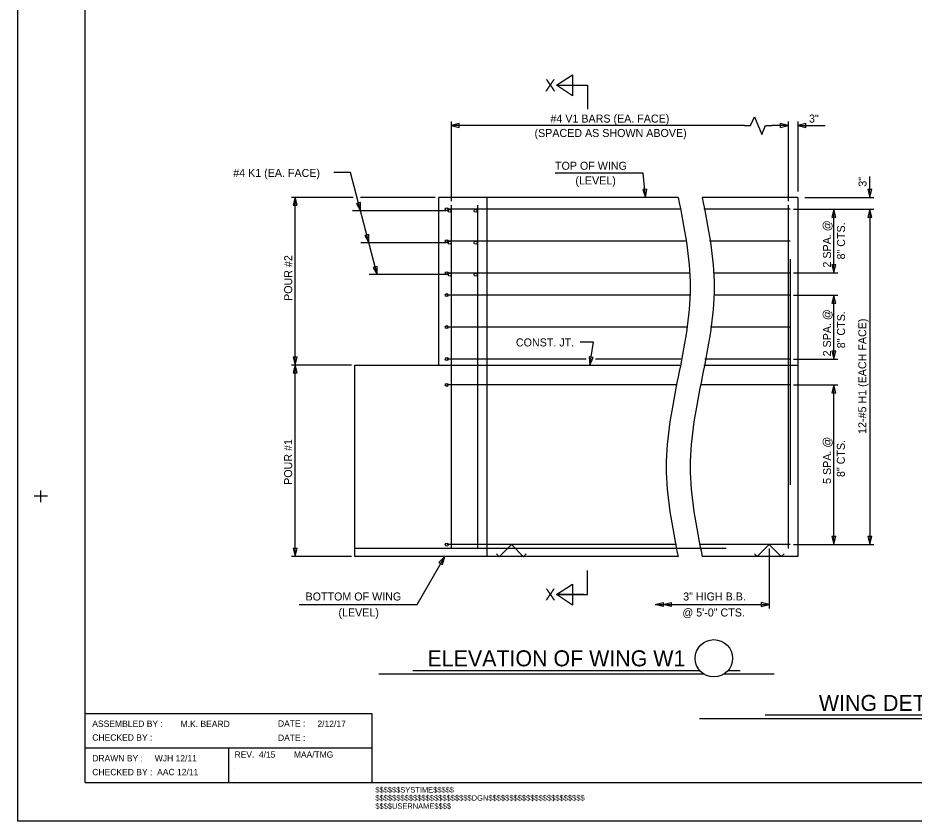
# Model space of a CAD drawing. Extents: x -41 to 251, y -169 to 237.
# Drawn here: x 0 to 18.71, y -98.91 to -82.14 of the extents above; entities that cross this region are included whole.
import ezdxf

# ---------------------------------------------------------------- set-up
doc = ezdxf.new("R2010")
doc.units = 0
for name, color, linetype in [('Arrowhead Terminators CELL', 7, 'Continuous'), ('Beam Bolsters CELL', 7, 'Continuous'), ('Default', 7, 'Continuous'), ('Dimension Lines', 7, 'Continuous'), ('Mis Object Lines', 7, 'Continuous'), ('Mis Object Lines Hidden', 7, 'Continuous'), ('Plan Sheet', 7, 'Continuous'), ('Plan Sheet CELL', 7, 'Continuous'), ('Plot Label CELL', 7, 'Continuous'), ('Plot Shape CELL', 7, 'Continuous'), ('Rebar K Bar Lines', 7, 'Continuous'), ('Rebar Lines', 7, 'Continuous'), ('Subtitle Text', 7, 'Continuous'), ('Text', 7, 'Continuous'), ('Title Text', 7, 'Continuous'), ('User Information Notes', 7, 'Continuous'), ('User Information Notes CELL', 7, 'Continuous')]:
    doc.layers.add(name, color=color, linetype=linetype)

# ---------------------------------------------------------------- blocks, each defined once
blk = doc.blocks.new('3 HIGH BEAM BOLSTER')
at = {"layer": 'Default'}
blk.add_lwpolyline([(-0.31, -0.192), (-0.251, -0.251), (0, 0), (0.251, -0.251), (0.31, -0.192)], dxfattribs=at)
blk = doc.blocks.new('SECSYM')
at = {"layer": 'Arrowhead Terminators CELL'}
blk.add_lwpolyline([(0, 0), (-2.48, 1.65), (-2.48, -1.65)], close=True, dxfattribs=at)

msp = doc.modelspace()

# ---------------------------------------------------------------- linework, layer by layer
at = {"layer": 'Arrowhead Terminators CELL'}
for points in [[(9.046, -84.389), (9.213, -84.43), (9.213, -84.347)], [(16.076, -84.389), (15.91, -84.347), (15.91, -84.43)], [(16.283, -84.389), (16.45, -84.43), (16.45, -84.347)], [(13.1, -85.889), (13.125, -85.719), (13.042, -85.727)], [(17.783, -85.889), (17.825, -85.722), (17.742, -85.722)], [(5.785, -85.889), (5.743, -86.055), (5.826, -86.055)], [(7.15, -86.17), (7.148, -85.998), (7.068, -86.02)], [(17.033, -86.139), (16.992, -86.305), (17.075, -86.305)], [(17.783, -86.139), (17.742, -86.305), (17.825, -86.305)], [(7.325, -86.836), (7.323, -86.665), (7.243, -86.686)], [(7.5, -87.503), (7.498, -87.332), (7.418, -87.353)], [(17.033, -87.466), (17.075, -87.299), (16.992, -87.299)], [(17.033, -87.93), (16.992, -88.096), (17.075, -88.096)], [(5.785, -89.389), (5.826, -89.222), (5.743, -89.222)], [(11.936, -89.389), (12.005, -89.232), (11.923, -89.218)], [(17.033, -89.264), (17.075, -89.097), (16.992, -89.097)], [(5.785, -89.389), (5.743, -89.555), (5.826, -89.555)], [(17.033, -89.805), (16.992, -89.971), (17.075, -89.971)], [(17.033, -93.139), (17.075, -92.972), (16.992, -92.972)], [(17.783, -93.139), (17.825, -92.972), (17.742, -92.972)], [(5.785, -93.389), (5.826, -93.222), (5.743, -93.222)], [(8.908, -93.389), (8.789, -93.512), (8.861, -93.553)], [(13.302, -94.389), (13.468, -94.347), (13.468, -94.43)], [(13.468, -94.389), (13.635, -94.347), (13.635, -94.43)], [(15.684, -94.389), (15.518, -94.347), (15.518, -94.43)]]:
    msp.add_lwpolyline(points, close=True, dxfattribs=at)
at = {"layer": 'Beam Bolsters CELL'}
msp.add_lwpolyline([(15.374, -93.33), (15.433, -93.389), (15.684, -93.139), (15.935, -93.389), (15.994, -93.33)], dxfattribs=at)
at = {"layer": 'Default'}
msp.add_lwpolyline([(15.167, -84.389), (15.295, -84.389), (15.377, -84.21), (15.531, -84.576), (15.608, -84.389), (15.739, -84.389)], dxfattribs=at)
at = {"layer": 'Dimension Lines'}
for p, q in [((11.245, -83.549), (11.888, -83.549)), ((11.888, -83.549), (11.888, -84.048)), ((9.046, -84.305), (9.046, -85.972)), ((16.076, -84.305), (16.076, -85.972)), ((16.283, -84.305), (16.283, -85.766)), ((15.167, -84.389), (9.046, -84.389)), ((16.076, -84.389), (15.739, -84.389)), ((16.283, -84.389), (16.848, -84.389)), ((6.941, -85.373), (6.596, -85.373)), ((7.5, -87.503), (6.941, -85.373)), ((13.05, -85.385), (11.217, -85.385)), ((13.1, -85.889), (13.05, -85.385)), ((17.783, -85.889), (17.783, -85.457)), ((7, -85.889), (5.713, -85.889)), ((5.785, -89.389), (5.785, -85.889)), ((8.713, -85.889), (7.15, -85.889)), ((16.423, -85.889), (17.867, -85.889)), ((8.931, -86.17), (6.984, -86.17)), ((16.189, -86.139), (17.867, -86.139)), ((17.033, -87.466), (17.033, -86.139)), ((17.783, -86.139), (17.783, -93.139)), ((8.931, -86.836), (7.159, -86.836)), ((8.931, -87.503), (7.334, -87.503)), ((16.189, -87.466), (17.117, -87.466)), ((16.189, -87.93), (17.117, -87.93)), ((17.033, -89.264), (17.033, -87.93)), ((12.017, -88.912), (11.736, -88.912)), ((11.936, -89.389), (12.017, -88.912)), ((6.963, -89.389), (5.713, -89.389)), ((5.785, -93.389), (5.785, -89.389)), ((16.189, -89.264), (17.117, -89.264)), ((16.189, -89.805), (17.117, -89.805)), ((17.033, -93.139), (17.033, -89.805)), ((16.189, -93.139), (17.867, -93.139)), ((15.684, -93.222), (15.684, -94.472)), ((6.963, -93.389), (5.712, -93.389)), ((11.888, -94.181), (11.888, -93.681)), ((11.81, -94.181), (11.245, -94.181)), ((11.245, -94.181), (11.888, -94.181)), ((13.302, -94.389), (15.684, -94.389))]:
    msp.add_line(p, q, dxfattribs=at)
msp.add_lwpolyline([(5.868, -94.389), (8.331, -94.389), (8.908, -93.389)], dxfattribs=at)
for points in [[(13.781, -85.889), (14.031, -87.764), (13.781, -89.639), (13.531, -91.514), (13.781, -93.389)], [(14.283, -85.889), (14.533, -87.764), (14.283, -89.639), (14.033, -91.514), (14.283, -93.389)]]:
    msp.add_spline(points, degree=3, dxfattribs=at)
at = {"layer": 'Mis Object Lines'}
for p, q in [((8.785, -89.389), (8.785, -85.889)), ((13.781, -85.889), (8.785, -85.889)), ((16.283, -85.889), (14.283, -85.889)), ((16.283, -85.889), (16.283, -93.389)), ((7.035, -93.389), (7.035, -89.389)), ((7.035, -89.389), (8.785, -89.389)), ((13.781, -93.389), (7.035, -93.389)), ((16.283, -93.389), (14.283, -93.389))]:
    msp.add_line(p, q, dxfattribs=at)
at = {"layer": 'Mis Object Lines Hidden'}
for p, q in [((9.785, -85.889), (9.785, -93.389)), ((8.785, -89.389), (13.819, -89.389)), ((14.321, -89.389), (16.283, -89.389))]:
    msp.add_line(p, q, dxfattribs=at)
at = {"layer": 'Plan Sheet CELL'}
for p, q in [((1.402, -98.104), (1.402, -70.174)), ((0.475, -92.25), (0.475, -92.009)), ((0.339, -92.119), (0.619, -92.119)), ((1.402, -96.661), (7.387, -96.661)), ((7.387, -96.661), (7.387, -97.382)), ((1.402, -97.382), (7.387, -97.382)), ((4.394, -97.382), (4.394, -98.104)), ((7.387, -97.382), (7.387, -98.104)), ((1.402, -98.104), (43.962, -98.104)), ((0, -98.91), (0, -98.91))]:
    msp.add_line(p, q, dxfattribs=at)
at = {"layer": 'Plot Shape CELL'}
msp.add_lwpolyline([(0, -69.65), (43.974, -69.65), (43.974, -98.91), (0, -98.91)], close=True, dxfattribs=at)
at = {"layer": 'Rebar K Bar Lines'}
for centre in [(9.014, -86.17), (9.556, -86.17), (9.014, -86.836), (9.556, -86.836), (9.014, -87.503), (9.556, -87.503)]:
    msp.add_circle(centre, 0.0312, dxfattribs=at)
at = {"layer": 'Rebar Lines'}
for p, q in [((13.819, -86.139), (8.952, -86.139)), ((9.046, -86.055), (9.046, -93.222)), ((9.59, -86.055), (9.59, -93.222)), ((16.117, -86.139), (14.321, -86.139)), ((16.076, -86.055), (16.076, -93.222)), ((13.934, -86.805), (8.952, -86.805)), ((16.117, -86.805), (14.436, -86.805)), ((14.02, -87.472), (8.952, -87.472)), ((16.117, -87.472), (14.522, -87.472)), ((14.028, -87.93), (8.952, -87.93)), ((16.117, -87.93), (14.53, -87.93)), ((13.955, -88.597), (8.952, -88.597)), ((16.117, -88.597), (14.457, -88.597)), ((11.865, -89.264), (8.952, -89.264)), ((13.839, -89.264), (12.053, -89.264)), ((16.117, -89.264), (14.341, -89.264)), ((13.757, -89.805), (8.952, -89.805)), ((16.117, -89.805), (14.259, -89.805)), ((13.744, -93.139), (8.952, -93.139)), ((16.117, -93.139), (14.246, -93.139))]:
    msp.add_line(p, q, dxfattribs=at)
for centre in [(8.952, -86.139), (8.952, -86.805), (8.952, -87.472), (8.952, -87.93), (8.952, -88.597), (8.952, -89.264), (8.952, -89.805), (8.952, -93.139)]:
    msp.add_circle(centre, 0.0312, dxfattribs=at)
at = {"layer": 'Title Text'}
for p, q in [((8.244, -95.763), (14.229, -95.763)), ((14.825, -95.763), (15.074, -95.763)), ((7.532, -95.837), (14.313, -95.837)), ((14.742, -95.837), (15.786, -95.837)), ((15.601, -96.694), (21.587, -96.694)), ((14.226, -96.768), (22.963, -96.768)), ((14.89, -96.768), (21.67, -96.768))]:
    msp.add_line(p, q, dxfattribs=at)
msp.add_circle((14.527, -95.512), 0.39, dxfattribs=at)
at = {"layer": 'User Information Notes'}
for p, q in [((4.524, -97.576), (4.524, -97.576)), ((4.524, -97.807), (4.524, -97.807)), ((4.524, -98.027), (4.524, -98.027))]:
    msp.add_line(p, q, dxfattribs=at)
at = {"layer": 'User Information Notes CELL'}
for p, q in [((16.117, -87.179), (16.117, -91.889)), ((14.785, -93.222), (7.035, -93.222))]:
    msp.add_line(p, q, dxfattribs=at)

# ---------------------------------------------------------------- block references
at = {"layer": 'Dimension Lines', "xscale": 0.1331292, "yscale": -0.133130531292, "rotation": 180}
for p in [(11.245, -83.549), (11.245, -94.181)]:
    msp.add_blockref('SECSYM', p, dxfattribs=at)
at = {"layer": 'Rebar Lines', "yscale": -1.00001, "rotation": 180}
msp.add_blockref('3 HIGH BEAM BOLSTER', (10.3, -93.139), dxfattribs=at)

# ---------------------------------------------------------------- texts
at = {"layer": 'Plan Sheet'}
msp.add_text('REV.  4/15        MAA/TMG', height=0.13124, dxfattribs=at).set_placement((4.524, -97.587))
at = {"layer": 'Plan Sheet CELL'}
for s, height, p in [('ASSEMBLED BY :', 0.13299, (1.552, -96.944)), ('DATE :', 0.133, (5.428, -96.94)), ('CHECKED BY :', 0.13299, (1.552, -97.232)), ('DATE :', 0.133, (5.428, -97.237)), ('DRAWN BY :     WJH 12/11', 0.13299, (1.552, -97.665)), ('CHECKED BY :  AAC 12/11', 0.13299, (1.552, -97.953))]:
    msp.add_text(s, height=height, dxfattribs=at).set_placement(p)
at = {"layer": 'Plot Label CELL'}
for s, height, p in [('$$$$$$SYSTIME$$$$$', 0.1131, (7.461, -98.314)), ('$$$$$$$$$$$$$$$$$$$$$$$DGN$$$$$$$$$$$$$$$$$$$$$$$', 0.11379, (7.461, -98.483)), ('$$$$USERNAME$$$$', 0.1131, (7.461, -98.653))]:
    msp.add_text(s, height=height, dxfattribs=at).set_placement(p)
at = {"layer": 'Subtitle Text'}
for p in [(11.001, -83.673), (11.001, -94.305)]:
    msp.add_text('X', height=0.25, dxfattribs=at).set_placement(p)
at = {"layer": 'Text'}
for s, rotation, p in [('#4 V1 BARS (EA. FACE)', 360, (11.116, -84.328)), ('3"', 360, (16.513, -84.327)), ('#4 K1 (EA. FACE)', 360, (4.494, -85.463)), ('TOP OF WING', 360, (11.211, -85.313)), ('(LEVEL)', 360, (11.637, -85.62)), ('3"', 90, (17.714, -85.667)), ('2 SPA. @', 90, (16.972, -87.354)), ('8" CTS.', 90, (17.265, -87.186)), ('POUR #2', 90, (5.725, -88.051)), ('2 SPA. @', 90, (16.972, -89.209)), ('8" CTS.', 90, (17.265, -89.04)), ('12-#5 H1 (EACH FACE)', 90, (17.709, -90.827)), ('CONST. JT.', 360, (10.395, -89.001)), ('5 SPA. @', 90, (16.973, -91.871)), ('POUR #1', 90, (5.724, -91.891)), ('8" CTS.', 90, (17.261, -91.728))]:
    msp.add_text(s, height=0.167, rotation=rotation, dxfattribs=at).set_placement(p)
for s, height, p in [(' (SPACED AS SHOWN ABOVE)', 0.167, (10.721, -84.629)), ('BOTTOM OF WING', 0.167, (6.004, -94.305)), ('3" HIGH B.B.', 0.167, (13.887, -94.305)), ('(LEVEL)', 0.167, (6.691, -94.639)), ('@ 5\'-0" CTS.', 0.167, (13.87, -94.639)), ('M.K. BEARD', 0.133, (3.395, -96.949)), ('2/12/17', 0.133, (6.252, -96.945))]:
    msp.add_text(s, height=height, dxfattribs=at).set_placement(p)
at = {"layer": 'Title Text'}
for s, p in [('ELEVATION OF WING W1', (8.549, -95.679)), ('WING DETAILS', (16.719, -96.61))]:
    msp.add_text(s, height=0.33388, dxfattribs=at).set_placement(p)

doc.saveas('drawing.dxf')
